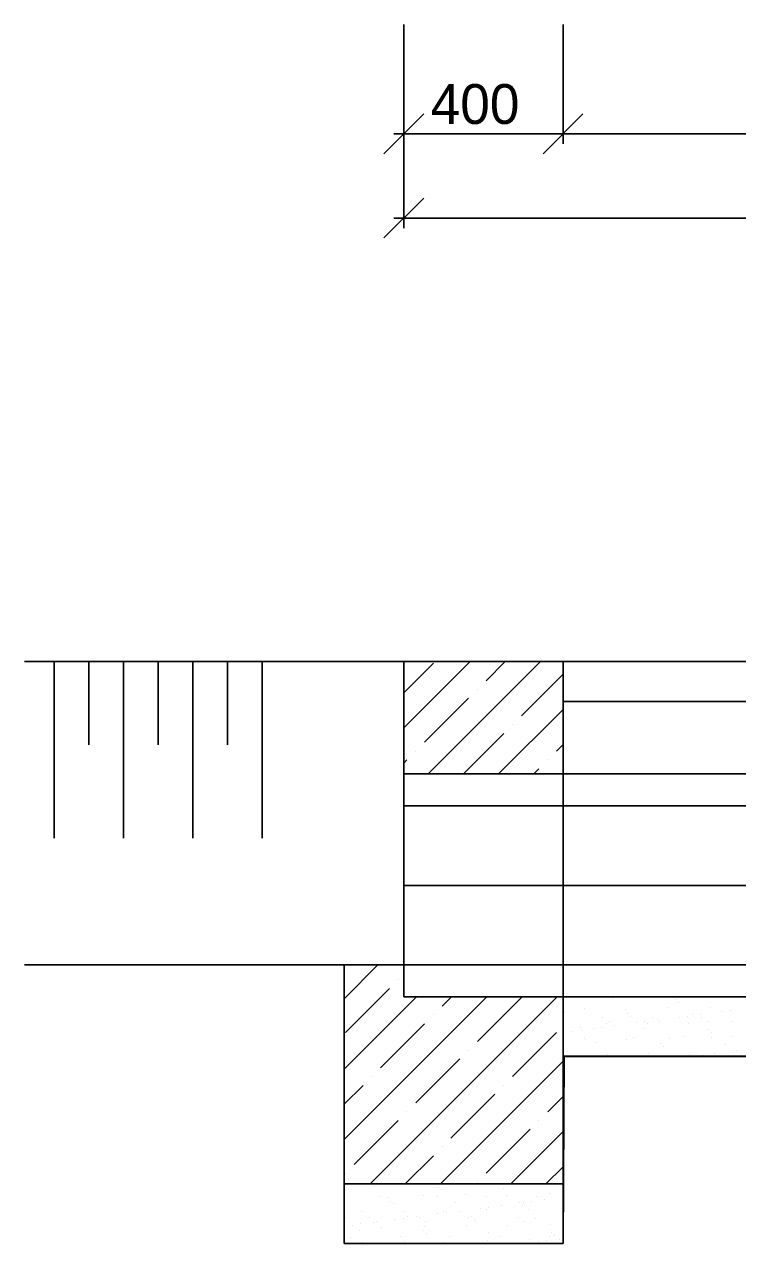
# Model space of a CAD drawing. Extents: x -2363 to 18637, y 14070 to 28920.
# Drawn here: x 2884 to 4675, y 15976 to 19039 of the extents above; entities that cross this region are included whole.
import ezdxf

# ---------------------------------------------------------------- set-up
doc = ezdxf.new("R2010")
doc.units = 0
for name, color, linetype in [('KÓTY', 7, 'Continuous'), ('OBRYS', 7, 'Continuous'), ('SJEZD', 7, 'Continuous'), ('ŠRAFY', 7, 'Continuous')]:
    doc.layers.add(name, color=color, linetype=linetype)

# ---------------------------------------------------------------- blocks, each defined once
blk = doc.blocks.new('_ARCHTICK')
blk.add_lwpolyline([(-0.5, -0.5), (0.5, 0.5)])

msp = doc.modelspace()

# ---------------------------------------------------------------- linework, layer by layer
at = {"layer": 'KÓTY'}
for p, q in [((3837, 19039.2), (3837, 18739.1)), ((3837, 19039.2), (3837, 18527.6)), ((4237, 19039.2), (4237, 18739.1)), ((4237, 19039.2), (4237, 18739.1)), ((3812, 18764.1), (4262, 18764.1)), ((4212, 18764.1), (8462, 18764.1)), ((3812, 18552.6), (8862, 18552.6))]:
    msp.add_line(p, q, dxfattribs=at)
at = {"layer": 'OBRYS'}
for p, q in [((3837, 17438.6), (8837, 17438.6)), ((3837, 17076.4), (3837, 17438.6)), ((8837, 17076.4), (3837, 17076.4)), ((2883.8, 16676.4), (9790.2, 16676.4)), ((3687, 16676.4), (3687, 15976.4)), ((4237, 15976.4), (4240, 16447.5)), ((4240, 16447.5), (8437, 16446.4)), ((3687, 15976.4), (4237, 15976.4))]:
    msp.add_line(p, q, dxfattribs=at)
at = {"layer": 'SJEZD'}
for p, q in [((9790.2, 17438.6), (2883.8, 17438.6)), ((3837, 17156.4), (3837, 17438.6)), ((4237, 17156.4), (4237, 17438.6)), ((8437, 17338.6), (4237, 17338.6)), ((8837, 17156.4), (3837, 17156.4)), ((3837, 17156.4), (3837, 16596.4)), ((3837, 17156.4), (3837, 16596.4)), ((4237, 16596.4), (4237, 17156.4)), ((8837, 17076.4), (3837, 17076.4)), ((8837, 16876.4), (3837, 16876.4)), ((3837, 16676.4), (2883.8, 16676.4)), ((2883.8, 16676.4), (9790.2, 16676.4)), ((3687, 15976.4), (3687, 16676.4)), ((3687, 16591.7), (3771.7, 16676.4)), ((8837, 16676.4), (3837, 16676.4)), ((3822.8, 16639.1), (3822.8, 16639.1)), ((3690.2, 16506.5), (3800.7, 16617)), ((3687, 16414.9), (3868.5, 16596.4)), ((3687, 16238.1), (4045.2, 16596.4)), ((3752, 16126.4), (4222, 16596.4)), ((8837, 16596.4), (3837, 16596.4)), ((3933.3, 16572.8), (3956.9, 16596.4)), ((4021.7, 16484.4), (4132.2, 16594.9)), ((4237, 15976.4), (4237, 16596.4)), ((3911.2, 16550.7), (3911.2, 16550.7)), ((3778.6, 16418.1), (3889.1, 16528.6)), ((4110.1, 16396), (4220.5, 16506.5)), ((3999.6, 16462.3), (3999.6, 16462.3)), ((3867, 16329.7), (3977.5, 16440.2)), ((3928.8, 16126.4), (4237, 16434.6)), ((8437, 16446.4), (4237, 16446.4)), ((3756.5, 16396), (3756.5, 16396)), ((3687, 16326.5), (3734.4, 16373.9)), ((4088, 16373.9), (4088, 16373.9)), ((3955.4, 16241.4), (4065.9, 16351.8)), ((4198.4, 16307.7), (4237, 16346.2)), ((3844.9, 16307.7), (3844.9, 16307.7)), ((3712.3, 16175.1), (3822.8, 16285.6)), ((4043.8, 16153), (4154.3, 16263.5)), ((4176.3, 16285.6), (4176.3, 16285.6)), ((4105.6, 16126.4), (4237, 16257.8)), ((3933.3, 16219.3), (3933.3, 16219.3)), ((3840.4, 16126.4), (3911.2, 16197.2)), ((3690.2, 16153), (3690.2, 16153)), ((4194, 16126.4), (4237, 16169.4)), ((4237, 16126.4), (3687, 16126.4)), ((4021.7, 16130.9), (4021.7, 16130.9)), ((4237, 15976.4), (3687, 15976.4))]:
    msp.add_line(p, q, dxfattribs=at)
at = {"layer": 'ŠRAFY'}
for p, q in [((2958.7, 17438.6), (2958.7, 16994.6)), ((3045.7, 17229.1), (3045.7, 17438.6)), ((3132.7, 17438.6), (3132.7, 16994.6)), ((3219.8, 17229.1), (3219.8, 17438.6)), ((3306.8, 17438.6), (3306.8, 16994.6)), ((3393.9, 17229.1), (3393.9, 17438.6)), ((3480.9, 17438.6), (3480.9, 16994.6)), ((3837, 17272), (4003.5, 17438.6)), ((3837, 17360.4), (3911.2, 17434.6)), ((3898.1, 17156.4), (4180.3, 17438.6)), ((4043.8, 17390.4), (4091.9, 17438.6)), ((4132.2, 17302), (4237, 17406.9)), ((4021.7, 17368.3), (4021.7, 17368.3)), ((3889.1, 17235.7), (3999.6, 17346.2)), ((4074.9, 17156.4), (4237, 17318.5)), ((4110.1, 17279.9), (4110.1, 17279.9)), ((3986.5, 17156.4), (4088, 17257.8)), ((3867, 17213.6), (3867, 17213.6)), ((4220.5, 17213.6), (4237, 17230.1)), ((3837, 17183.6), (3844.9, 17191.5)), ((4198.4, 17191.5), (4198.4, 17191.5)), ((4163.3, 17156.4), (4176.3, 17169.4)), ((4257.3, 16595.2), (4257.3, 16595.2)), ((4360.1, 16591), (4360.1, 16591)), ((4381.9, 16595.5), (4381.9, 16595.5)), ((4506.4, 16595.7), (4506.4, 16595.7)), ((4520.1, 16589.7), (4520.1, 16589.7)), ((4527.5, 16582.9), (4527.5, 16582.9)), ((4606.5, 16570.7), (4606.5, 16570.7)), ((4631, 16595.9), (4631, 16595.9)), ((4239.8, 16555.9), (4239.8, 16555.9)), ((4291.4, 16566), (4291.4, 16566)), ((4336.6, 16544.7), (4336.6, 16544.7)), ((4393.7, 16565.5), (4393.7, 16565.5)), ((4399.9, 16554.5), (4399.9, 16554.5)), ((4407.2, 16547.8), (4407.2, 16547.8)), ((4461.1, 16545), (4461.1, 16545)), ((4501.8, 16569.4), (4501.8, 16569.4)), ((4528.4, 16545.3), (4528.4, 16545.3)), ((4549.2, 16548.1), (4549.2, 16548.1)), ((4562.3, 16551), (4562.3, 16551)), ((4581.8, 16552.4), (4581.8, 16552.4)), ((4585.7, 16545.2), (4585.7, 16545.2)), ((4636.1, 16559.5), (4636.1, 16559.5)), ((4656.9, 16562.3), (4656.9, 16562.3)), ((4237.5, 16524.6), (4237.5, 16524.6)), ((4258.7, 16509.8), (4258.7, 16509.8)), ((4279.6, 16519.4), (4279.6, 16519.4)), ((4287, 16512.7), (4287, 16512.7)), ((4313.1, 16517), (4313.1, 16517)), ((4333.9, 16519.7), (4333.9, 16519.7)), ((4345.5, 16528.5), (4345.5, 16528.5)), ((4353.4, 16534), (4353.4, 16534)), ((4366.4, 16524), (4366.4, 16524)), ((4420.7, 16531.2), (4420.7, 16531.2)), ((4441.6, 16533.9), (4441.6, 16533.9)), ((4442, 16515.9), (4442, 16515.9)), ((4450.2, 16529.8), (4450.2, 16529.8)), ((4474.1, 16538.2), (4474.1, 16538.2)), ((4478, 16534.2), (4478, 16534.2)), ((4552.5, 16529.3), (4552.5, 16529.3)), ((4602.1, 16514.5), (4602.1, 16514.5)), ((4602.6, 16534.4), (4602.6, 16534.4)), ((4660.6, 16533.2), (4660.6, 16533.2)), ((4289.6, 16495.1), (4289.6, 16495.1)), ((4293.9, 16488.9), (4293.9, 16488.9)), ((4321.8, 16480.8), (4321.8, 16480.8)), ((4396.3, 16488.4), (4396.3, 16488.4)), ((4414.2, 16495.3), (4414.2, 16495.3)), ((4481.9, 16479.4), (4481.9, 16479.4)), ((4504.3, 16492.3), (4504.3, 16492.3)), ((4538.7, 16495.5), (4538.7, 16495.5)), ((4609, 16493.7), (4609, 16493.7)), ((4609.5, 16507.8), (4609.5, 16507.8)), ((4663.3, 16495.8), (4663.3, 16495.8)), ((4240, 16447.5), (4240, 16447.5)), ((4348, 16451.4), (4348, 16451.4)), ((4452.7, 16452.8), (4452.7, 16452.8)), ((4489.2, 16472.7), (4489.2, 16472.7)), ((4555.1, 16452.3), (4555.1, 16452.3)), ((4586.1, 16449.4), (4586.1, 16449.4)), ((4618.6, 16453.7), (4618.6, 16453.7)), ((4644.3, 16475.9), (4644.3, 16475.9)), ((4663.1, 16456.2), (4663.1, 16456.2)), ((4673, 16460.8), (4673, 16460.8)), ((4565.3, 16446.6), (4565.3, 16446.6)), ((3690.8, 16124.4), (3690.8, 16124.4)), ((3764.3, 16119.9), (3764.3, 16119.9)), ((3924.4, 16118.5), (3924.4, 16118.5)), ((3931.7, 16111.8), (3931.7, 16111.8)), ((4086.8, 16115), (4086.8, 16115)), ((3778.7, 16093.6), (3778.7, 16093.6)), ((3796, 16093.3), (3796, 16093.3)), ((3804.1, 16083.4), (3804.1, 16083.4)), ((3886.8, 16097.5), (3886.8, 16097.5)), ((3920.6, 16093.5), (3920.6, 16093.5)), ((3966.5, 16079.9), (3966.5, 16079.9)), ((3991.5, 16098.8), (3991.5, 16098.8)), ((4045.1, 16093.7), (4045.1, 16093.7)), ((4093.8, 16098.3), (4093.8, 16098.3)), ((4158.4, 16082.4), (4158.4, 16082.4)), ((4169.7, 16094), (4169.7, 16094)), ((4190.9, 16086.6), (4190.9, 16086.6)), ((4201.8, 16102.2), (4201.8, 16102.2)), ((3730.5, 16056.6), (3730.5, 16056.6)), ((3811.5, 16076.7), (3811.5, 16076.7)), ((3835.2, 16057.9), (3835.2, 16057.9)), ((3922.2, 16051.3), (3922.2, 16051.3)), ((3937.5, 16057.4), (3937.5, 16057.4)), ((3943.1, 16054), (3943.1, 16054)), ((3975.6, 16058.3), (3975.6, 16058.3)), ((4029.9, 16065.5), (4029.9, 16065.5)), ((4045.6, 16061.3), (4045.6, 16061.3)), ((4050.7, 16068.2), (4050.7, 16068.2)), ((4083.3, 16072.5), (4083.3, 16072.5)), ((4126.6, 16078.5), (4126.6, 16078.5)), ((4134, 16071.8), (4134, 16071.8)), ((4137.6, 16079.6), (4137.6, 16079.6)), ((4150.3, 16062.7), (4150.3, 16062.7)), ((3691.2, 16041.6), (3691.2, 16041.6)), ((3706.9, 16022.9), (3706.9, 16022.9)), ((3727.7, 16025.7), (3727.7, 16025.7)), ((3750.7, 16042.6), (3750.7, 16042.6)), ((3760.2, 16029.9), (3760.2, 16029.9)), ((3767.6, 16031.8), (3767.6, 16031.8)), ((3814.6, 16037.1), (3814.6, 16037.1)), ((3835.4, 16039.8), (3835.4, 16039.8)), ((3846.3, 16044.8), (3846.3, 16044.8)), ((3867.9, 16044.1), (3867.9, 16044.1)), ((3875.3, 16042.8), (3875.3, 16042.8)), ((3889.3, 16020.4), (3889.3, 16020.4)), ((3892.1, 16032), (3892.1, 16032)), ((3994, 16021.8), (3994, 16021.8)), ((3999.8, 16043), (3999.8, 16043)), ((4006.3, 16043.4), (4006.3, 16043.4)), ((4013.7, 16036.6), (4013.7, 16036.6)), ((4016.7, 16032.3), (4016.7, 16032.3)), ((4096.3, 16021.3), (4096.3, 16021.3)), ((4124.4, 16043.2), (4124.4, 16043.2)), ((4141.3, 16032.5), (4141.3, 16032.5)), ((4168.8, 16039.9), (4168.8, 16039.9)), ((4204.4, 16025.2), (4204.4, 16025.2)), ((3703.7, 15992.9), (3703.7, 15992.9)), ((3726, 16009.7), (3726, 16009.7)), ((3781.3, 16016.5), (3781.3, 16016.5)), ((3828.3, 15993.1), (3828.3, 15993.1)), ((3886.1, 16008.3), (3886.1, 16008.3)), ((3893.5, 16001.5), (3893.5, 16001.5)), ((3952.9, 15993.3), (3952.9, 15993.3)), ((4048.5, 16004.8), (4048.5, 16004.8)), ((4077.4, 15993.6), (4077.4, 15993.6)), ((4202, 15993.8), (4202, 15993.8)), ((4208.6, 16003.4), (4208.6, 16003.4)), ((4215.9, 15996.6), (4215.9, 15996.6)), ((4227.8, 15987.9), (4227.8, 15987.9)), ((3733, 15979.5), (3733, 15979.5)), ((3837.7, 15980.9), (3837.7, 15980.9)), ((3940.1, 15980.4), (3940.1, 15980.4)), ((4048.1, 15984.3), (4048.1, 15984.3)), ((4152.8, 15985.6), (4152.8, 15985.6)), ((4174.5, 15980.9), (4174.5, 15980.9)), ((4195.3, 15983.7), (4195.3, 15983.7))]:
    msp.add_line(p, q, dxfattribs=at)

# ---------------------------------------------------------------- block references
at = {"layer": 'KÓTY', "xscale": 100, "yscale": 100, "rotation": 180}
for p in [(3837, 18764.1), (4237, 18764.1), (3837, 18552.6)]:
    msp.add_blockref('_ARCHTICK', p, dxfattribs=at)
at = {"layer": 'KÓTY', "xscale": 100, "yscale": 100}
msp.add_blockref('_ARCHTICK', (4237, 18764.1), dxfattribs=at)

# ---------------------------------------------------------------- texts
at = {"layer": 'KÓTY'}
msp.add_text('400', height=100, dxfattribs=at).set_placement((3904.3, 18789.1))

doc.saveas('drawing.dxf')
